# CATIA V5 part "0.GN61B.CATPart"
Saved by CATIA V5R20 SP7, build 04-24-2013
Part number: 0.GN61B
Material "Nessuno"
Bounding box of the stored display mesh (mm): x 0 to 150.807, y -131.181 to 0, z -91.151 to 75.737
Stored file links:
  C:\Users\designer2\Desktop\Ottobre 2022\25-10-2022\04\Yori Evo 48V\0.GN61B.CATPart
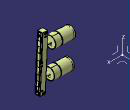
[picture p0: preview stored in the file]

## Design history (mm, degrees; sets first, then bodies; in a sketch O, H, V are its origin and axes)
AxisSystem1: origin (0, 0, 0), X (1, 0, 0), Y (0, 1, 0), Z (0, 0, 1)
Set1
  DatumSurface1
Body1 (main body), material "Nessuno"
